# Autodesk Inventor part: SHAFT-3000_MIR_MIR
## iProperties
Created: 2007-08
Part Number: SHAFT-3000_MIR_MIR
Material: Stainless Steel
Document SubType Name: Modeling
Density: 8.08 g/cm^3
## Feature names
1. Derived Body1 [Tagging]
